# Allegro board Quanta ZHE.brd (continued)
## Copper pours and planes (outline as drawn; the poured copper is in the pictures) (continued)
N30417403 on BOTTOM (solid shape): 125.91,17.6 125.91,13.22 125.69,12.99 122.82,12.99 122.82,12.99 121.63,12.99 121.56,13.05 121.56,16.72 121.61,16.76 122.53,16.76 122.67,16.9 122.67,17.58 122.86,17.77 125.75,17.77
N30417534 on TOP (solid shape): 139.1,12.24 139.1,9.96 138.97,9.83 138.46,9.83 138.34,9.96 138.34,12.24 138.46,12.37 138.97,12.37
N30954436 on BOTTOM (solid shape): 162.97,55.04 162.97,51.2 162.97,51.19 162.94,51.15 162.94,49.69 162.93,49.67 162.92,49.66 162.85,49.58 160.81,49.58 160.69,49.71 160.69,50.72 160.81,50.85 161.58,50.85 161.7,50.98 161.7,55.04 161.83,55.17 162.85,55.17
N32459164 on BOTTOM (solid shape): 151.04,24.48 151.71,24.48 151.87,24.32 151.87,23.51 151.76,23.4 150.47,23.4 149.62,24.24 149.62,24.98 149.74,25.09 150.43,25.09
N32459174 on TOP (solid shape): 152.64,33.73 153.42,33.73 153.58,33.58 153.58,30.43 153.47,30.33 152.03,30.33 151.92,30.43 151.92,31.75 151.86,31.82 151.86,31.85 151.82,31.85 151.61,32.07 151.61,33.87 151.64,33.91 152.46,33.91
N32459174 on BOTTOM (solid shape): 153.42,33.7 153.42,32.89 153.83,32.48 153.83,32.31 153.96,32.18 154.01,32.18 154.03,32.16 157.79,32.16 158.02,31.93 158.02,31.69 158.04,31.67 158.04,31.44 158.93,30.55 158.93,27.51 158.82,27.39 155.66,27.39 155.53,27.52 155.53,29.82 154.86,30.49 154.1,30.49 154.09,30.49 153.96,30.53 153.82,30.51 153.81,30.51 152.93,30.51 152.31,31.14 152.31,33.7 152.43,33.83 153.3,33.83
N32459193 on TOP (solid shape): 155.77,19.19 155.77,17.51 155.67,17.41 153.28,17.41 153.26,17.4 151.77,17.4 147.68,17.4 147.23,17.85 147.23,19.1 147.35,19.23 155.73,19.23
N32459193 on BOTTOM (solid shape): outline of 201 points within 144.56,14.78 157.39,19.48
N33998046 on TOP (solid shape): 40.11,70.74 40.11,70 40.05,69.93 39.12,69.93 39.12,69.92 38.46,69.92 38.35,70.04 38.35,70.75 38.39,70.79 40.06,70.79
N33998046 on BOTTOM (solid shape): 39.02,70.41 39.02,69.77 38.89,69.65 37.62,69.65 37.5,69.77 37.5,70.36 37.51,70.39 37.55,70.41 38.39,70.41 38.51,70.53 38.89,70.53
N34971086 on BOTTOM (solid shape): 175.04,74.34 175.04,72.69 175.17,72.57 175.37,72.57 175.39,72.56 175.4,72.55 175.67,72.44 175.94,72.55 175.96,72.56 175.98,72.57 176.01,72.57 176.04,72.55 176.28,72.44 176.58,72.53 176.61,72.52 176.69,72.44 176.69,71.3 176.56,71.17 175.17,71.17 175.04,71.04 175.04,70.53 174.91,70.41 173.64,70.41 173.51,70.53 173.51,71.04 173.39,71.17 169.96,71.17 169.32,70.53 169.32,69.65 169.2,69.52 169.07,69.65 169.07,71.68 170.21,72.82 170.21,75.23 170.47,75.49 173.9,75.49
N35712957 on BOTTOM (solid shape): 51.72,17.76 51.72,16.38 51.86,16.24 51.86,14.84 51.58,14.56 51.58,13.85 50.5,12.77 50.5,11.21 50.32,11.02 48.68,11.02 48.29,10.64 48.29,7.86 48.39,7.76 48.39,6.13 48.39,6.13 48.39,5.1 48.22,5.1 48.22,6.26 48.19,6.29 48.01,6.29 47.98,6.25 47.98,5.1 47.72,5.1 47.72,6.43 47.16,7 47.16,11.29 47.29,11.42 47.9,11.42 50.15,13.67 50.2,13.72 50.2,15.63 50.58,16.01 50.58,16.36 50.31,16.63 50.31,17.87 50.47,18.03 51.45,18.03
N35788414 on BOTTOM (solid shape): 161.93,67.51 161.93,66.52 162.97,65.48 162.97,59.49 162.85,59.36 162.08,59.36 161.96,59.49 161.96,64.95 160.81,66.09 160.81,67.49 160.94,67.61 161.83,67.61
N36056010 on BOTTOM (solid shape): 20.19,66.94 24.16,66.94 24.28,66.83 24.28,63.03 24.21,62.96 21.67,62.96 21.5,63.14 21.5,65.38 21.11,65.76 19.79,65.76 19.36,66.19 18.6,66.19 18.52,66.27 18.52,67.08 18.57,67.13 20,67.13
N36056032 on BOTTOM (solid shape): 19.58,62.83 21.33,62.83 21.75,62.41 21.75,61.77 21.5,61.52 20.61,61.52 20.39,61.3 20.25,61.3 20.03,61.08 19.88,60.85 19.85,60.58 19.82,60.51 19.74,60.48 19.34,60.48 19.11,60.7 19.11,61.11 18.6,61.62 18.6,62.84 18.68,62.91 19.49,62.91
N36056070 on BOTTOM (solid shape): 16.9,68.07 16.9,66.19 17.3,65.78 17.3,64.69 17.2,64.59 16.42,64.59 15.91,65.1 15.91,65.71 16.06,65.86 16.06,67.92 16.31,68.17 16.8,68.17
N40708508 on TOP (solid shape): 167.55,74.09 167.55,68.88 167.16,68.5 163.3,68.5 163.27,68.52 163.22,68.54 163.18,68.55 163.1,68.63 163.1,70 163.43,70 163.43,69.95 163.45,69.89 163.47,69.84 163.49,69.79 163.53,69.75 163.57,69.71 163.61,69.67 163.66,69.65 163.71,69.63 163.77,69.62 163.83,69.62 163.88,69.62 163.93,69.64 163.99,69.66 164.03,69.69 164.08,69.73 164.11,69.77 164.14,69.81 164.17,69.86 164.18,69.92 164.19,69.97 164.19,70.03 164.18,70.08 164.17,70.14 164.14,70.19 164.11,70.23 164.08,70.28 164.03,70.31 163.99,70.34 163.93,70.36 163.88,70.38 163.83,70.38 163.77,70.38 163.71,70.37 163.66,70.35 163.61,70.33 163.57,70.29 163.53,70.26 163.49,70.21 163.47,70.16 163.45,70.11 163.43,70.06 163.43,70 163.1,70 163.1,71.8 163.18,71.88 163.96,71.88 164.09,72.01 164.42,72.01 164.55,71.88 166.01,71.88 166.28,72.15 166.28,72.74 166.47,72.94 166.47,74.13 166.5,74.17 167.47,74.17
N40708508 on BOTTOM (solid shape): 167.29,72.82 167.29,69.42 166.99,69.11 166.99,68.6 166.88,68.5 163.25,68.5 163.1,68.65 163.1,69.11 163.31,69.32 163.31,69.32 163.58,69.59 163.79,69.59 163.81,69.62 163.83,69.62 164.19,69.96 163.91,70.37 163.9,70.37 163.87,70.4 163.87,72.58 164.37,73.07 167.04,73.07

Small or netless copper shapes (teardrops, artwork), in the pictures only: 46 on TOP, 6 on BOTTOM, 84 on IN2, 5 on IN3

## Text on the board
Ref Des/Silkscreen Bottom: MODEL:ZHE | DA0ZHEMB8D0 REV:D
User.Comments: PARTITION_2 | PARTITION_3 | 20.0x28.0 | 20.0x63.0 | 24.0x63.0 | 31.0x69.0 | 31.0x87.0 | 24.0x91.0 | 31.0x94.0 | 40.0x43.0 | 94.0x106.0 | PCB OUTLINE | 188.00 | 108.00
Ref Des/Silkscreen Top: DA0ZHEMB8D0 REV:D
BODY_CENTER: TOP LIMIT VIEW
DISPLAY_TOP: BTM LIMIT VIEW
User.6: TOP COMPONENT VIEW | LED | HALL SENSOR
User.7: BTM COMPONENT VIEW | FAN CONN | DC-IN CONN | KEY BOARD | CONN | DHH | RJ45 | TP | USB 2.0 | BATT | USB 3.0 | HDMI | KB | backlight | SPK | LVDS CONN | AUDIO | SD card | LID | SWITCH
User.8: LED | HALL SENSOR | TOP COMPONENT VIEW
User.9: FAN CONN | DC-IN CONN | KEY BOARD | CONN | DHH | RJ45 | TP | USB 2.0 | BATT | USB 3.0 | HDMI | KB | backlight | SPK | LVDS CONN | AUDIO | SD card | LID | SWITCH | BTM COMPONENT VIEW
User.12: +3VPCU | GND | +VIN | +VNN | +VCC_VCCGI | +5V_S5 | +1.2VSUS | +5V | ADOGND | VA
User.25: TOP LIMIT VIEW
User.26: BTM LIMIT VIEW
User.27: GND | ADOGND
User.28: GND | ADOGND
User.31: REV:A-4
User.32: GND | ADOGND
User.33: VA | GND | +VNN | +VCC_VCCGI | +5V_S5 | +3VPCU | +1.2VSUS | +VIN | +5V | ADOGND
User.34: GND | ADOGND
User.45: PadStack_Check:Aug 14 12:05:37 2017 | TP check:Aug 14 11:01:29 2017 | XY-Check acute:Aug 14 12:18:09 2017 | XY-Create nettxt:Aug 14 11:43:21 2017 | XY-Create plane:Aug 14 13:23:22 2017 | XY-Dxf to pin check:Aug 14 11:29:23 2017 | XY-PadStack_Check:Aug 14 12:05:37 2017 | XY-Plane net check:Aug 14 12:05:58 2017 | XY-Prop check:Aug 14 12:19:11 2017 | XY-Symbol cross:Aug 14 12:08:07 2017 | XY-TP check:Aug 14 11:01:29 2017 | XY-shape min check:Aug 14 12:04:48 2017 | check acute:Aug 14 12:18:09 2017 | create nettxt:Aug 14 11:43:21 2017 | create plane:Aug 14 13:23:22 2017 | dxf to pin check:Aug 14 11:29:23 2017 | plane net check:Aug 14 12:05:58 2017 | prop check:Aug 14 12:19:11 2017 | shape min check:Aug 14 12:04:48 2017 | symbol cross:Aug 14 12:08:07 2017 | PT_TOP | PT_BOT | FIGURE | TYPE | Circle | SIZE | 10.0 | 12.0 | 14.0 | 24.0 | 31.0 | 32.0 | 35.0 | 39.0 | 40.0 | 98.0 | 126.0 | 138.0 | 142.0 | 144.0 | 37.0 | 38.0 | 43.0 | 47.0 | 48.0 | 63.0 | 67.0 | 94.0 | DRILL CHART: TOP to BOTTOM | ALL UNITS ARE IN MILS | PLATED | NON-PLATED | ROTATION | - | QTY | 3231 | 14 | 4 | 340 | 48 | 9 | 8 | 2 | 1 | 3 | 3696 | Oblong | 46.0x24.0 | 47.0x24.0 | 51.0x24.0 | 71.0x31.0 | 75.0x31.0 | 106.0x94.0 | 90.000 | 0.000 | 19 | 6 | 53 | TOTAL HOLES:
